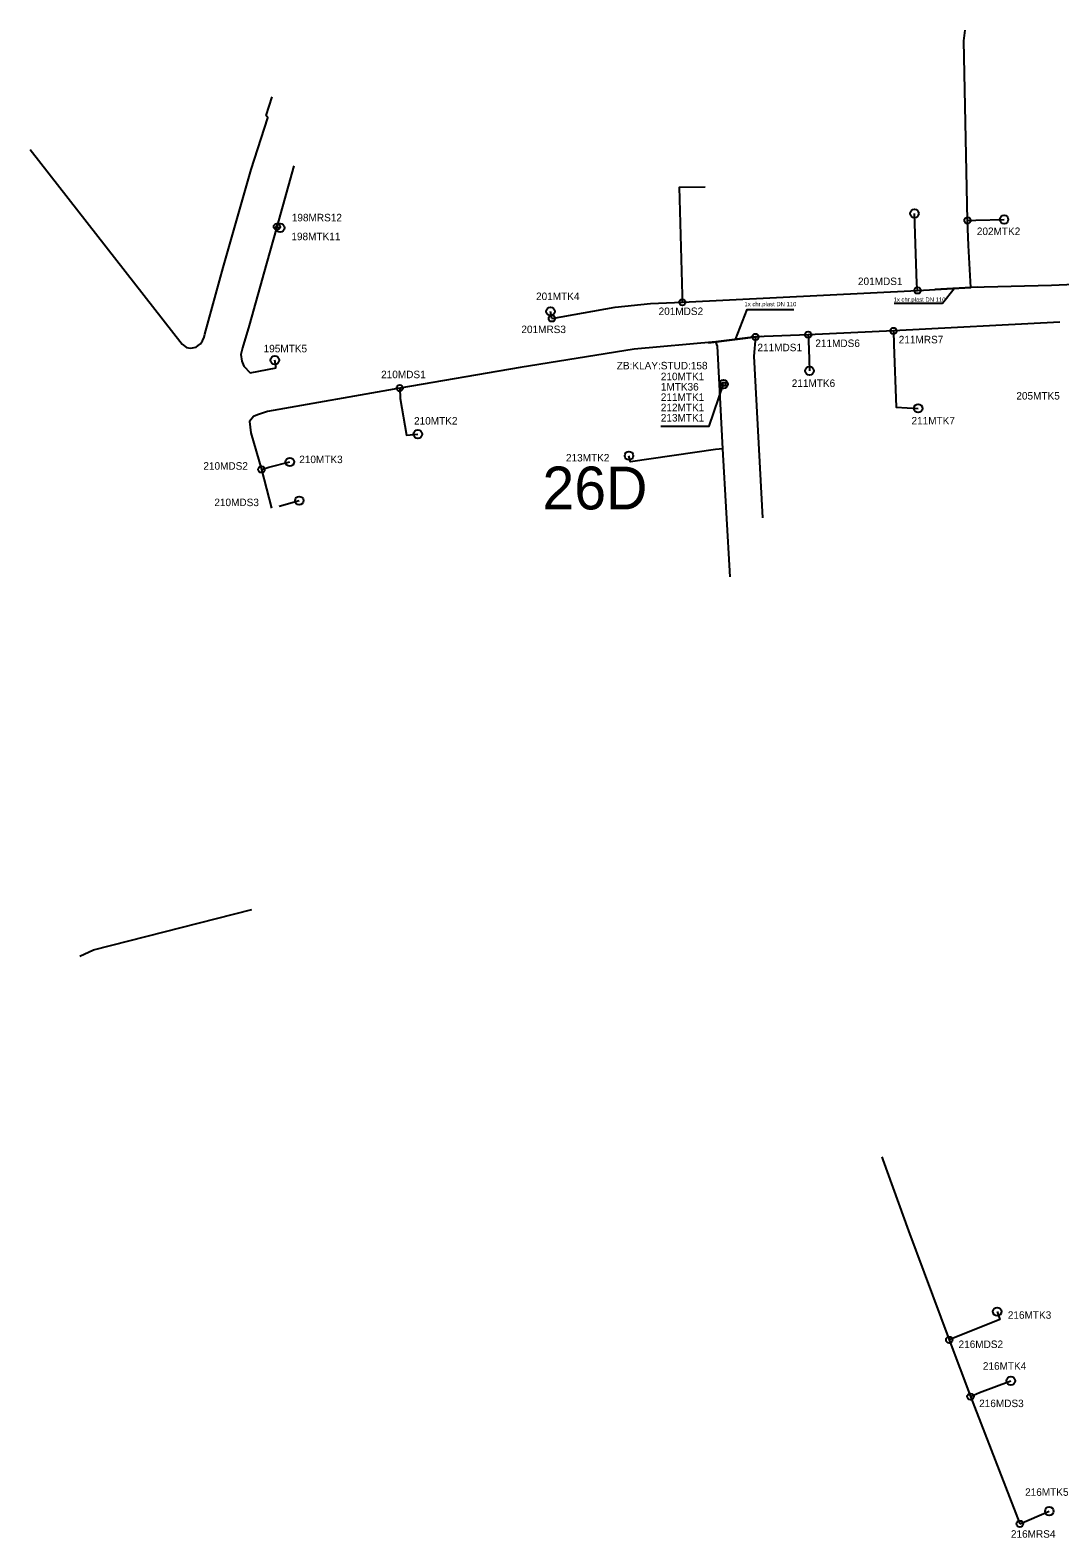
# Model space of a CAD drawing. Extents: x -835291 to -833547, y -1108367 to -1106510.
# Drawn here: x -834054.6 to -833814, y -1108018.1 to -1107665.9 of the extents above; entities that cross this region are included whole.
import ezdxf

# ---------------------------------------------------------------- set-up
doc = ezdxf.new("R2010")
doc.units = 0
for name, color, linetype in [('Vrstva 1', 7, 'Continuous'), ('Vrstva 12', 7, 'Continuous'), ('Vrstva 13', 7, 'Continuous'), ('Vrstva 18', 7, 'Continuous'), ('Vrstva 21', 7, 'Continuous'), ('Vrstva 3', 7, 'Continuous'), ('Vrstva 5', 7, 'Continuous')]:
    doc.layers.add(name, color=color, linetype=linetype)

msp = doc.modelspace()

# ---------------------------------------------------------------- linework, layer by layer
at = {"layer": 'Vrstva 1'}
for p, q in [((-833992.95, -1107697.61), (-833996.91, -1107711.85)), ((-833835.57, -1107710.38), (-833833.62, -1107710.35)), ((-833996.91, -1107711.85), (-833996.15, -1107712.11)), ((-833902.2, -1107729.52), (-833847.29, -1107726.75)), ((-833902.2, -1107729.52), (-833902.17, -1107727.88)), ((-833847.29, -1107726.75), (-833847.41, -1107725.17)), ((-833847.29, -1107726.75), (-833834.83, -1107726.06)), ((-833932.68, -1107733.29), (-833932.99, -1107731.64)), ((-833814.02, -1107734.16), (-833852.9, -1107736.21)), ((-833885.12, -1107737.61), (-833894.39, -1107738.75)), ((-833872.82, -1107737.08), (-833885.12, -1107737.61)), ((-833852.9, -1107736.21), (-833872.82, -1107737.08)), ((-833872.82, -1107737.08), (-833872.64, -1107740.35)), ((-833852.9, -1107736.21), (-833852.82, -1107739.35)), ((-834003.19, -1107745.97), (-833997.11, -1107744.83)), ((-833997.11, -1107744.83), (-833997.41, -1107743.01)), ((-833968.23, -1107749.58), (-833968.11, -1107751.98)), ((-833893.56, -1107748.69), (-833892.56, -1107748.65)), ((-833892.74, -1107763.77), (-833893.56, -1107748.69)), ((-833892.74, -1107763.77), (-833894.48, -1107763.9)), ((-833891.07, -1107793.68), (-833892.74, -1107763.77)), ((-834000.53, -1107768.56), (-833998.82, -1107768.04)), ((-834000.53, -1107768.56), (-833998.17, -1107777.62)), ((-833839.85, -1107971.91), (-833834.9, -1107985.16)), ((-833834.9, -1107985.16), (-833832.76, -1107984.23)), ((-833834.9, -1107985.16), (-833823.37, -1108014.89)), ((-833823.37, -1108014.89), (-833821.22, -1108013.92))]:
    msp.add_line(p, q, dxfattribs=at)
for points in [[(-833835.57, -1107710.38), (-833836.47, -1107668.46), (-833836.13, -1107665.94)], [(-834054.56, -1107693.86), (-834019.06, -1107739.26), (-834018.04, -1107740.06), (-834017.07, -1107740.22), (-834015.81, -1107740.02), (-834015.28, -1107739.62), (-834014.75, -1107739.22), (-834014.27, -1107738.52), (-834013.88, -1107737.65), (-834013.75, -1107736.97), (-834009.44, -1107721.37), (-834002.94, -1107698.53), (-833999, -1107686.41), (-833999.43, -1107685.91), (-833998.01, -1107681.53)], [(-833834.83, -1107726.06), (-833835.36, -1107716.25), (-833835.57, -1107710.38)], [(-833996.91, -1107711.85), (-833999.31, -1107720.42), (-834003.39, -1107734.93)], [(-833780.16, -1107724.03), (-833815.95, -1107725.61), (-833834.83, -1107726.06)], [(-833932.68, -1107733.29), (-833917.9, -1107730.65), (-833909.61, -1107729.79), (-833902.2, -1107729.52)], [(-834003.39, -1107734.93), (-834004.94, -1107740.19), (-834005.38, -1107741.69), (-834005.14, -1107743.29)], [(-833894.39, -1107738.75), (-833913.49, -1107740.44), (-833940.08, -1107744.71), (-833968.23, -1107749.58)], [(-833893.56, -1107748.69), (-833893.99, -1107739.8), (-833894.39, -1107738.75)], [(-833885.12, -1107737.61), (-833885.51, -1107742.13), (-833883.47, -1107779.86)], [(-834005.14, -1107743.29), (-834005.14, -1107743.29), (-834005.14, -1107743.29), (-834004.66, -1107744.45), (-834003.19, -1107745.97)], [(-833968.23, -1107749.58), (-833999.15, -1107754.99), (-834001.44, -1107755.82)], [(-834001.44, -1107755.82), (-834002.39, -1107756.17), (-834003.31, -1107757.37), (-834002.98, -1107760), (-834000.53, -1107768.56)], [(-834042.98, -1107882.24), (-834039.74, -1107880.76), (-834002.78, -1107871.35)], [(-833855.59, -1107929.16), (-833855.41, -1107929.83), (-833849.4, -1107946.41), (-833845.71, -1107956.24), (-833839.85, -1107971.91)]]:
    msp.add_lwpolyline(points, dxfattribs=at)
at = {"layer": 'Vrstva 12'}
for p, q in [((-833833.31, -1107725.97), (-833843.2, -1107726.52)), ((-833896.11, -1107738.97), (-833883.79, -1107737.45))]:
    msp.add_line(p, q, dxfattribs=at)
at = {"layer": 'Vrstva 13'}
for points in [[(-833852.72, -1107729.69), (-833841.47, -1107729.69), (-833838.72, -1107726.27)], [(-833889.75, -1107738.18), (-833887.05, -1107731.17), (-833876.13, -1107731.17)]]:
    msp.add_lwpolyline(points, dxfattribs=at)
at = {"layer": 'Vrstva 21'}
for p, q in [((-833847.41, -1107725.17), (-833848, -1107708.79)), ((-833833.62, -1107710.35), (-833827.06, -1107710.18)), ((-833872.64, -1107740.35), (-833872.5, -1107745.53)), ((-833998.82, -1107768.04), (-833993.89, -1107766.82)), ((-833996.42, -1107777.17), (-833991.68, -1107775.85)), ((-833832.76, -1107984.23), (-833825.45, -1107981.48)), ((-833821.22, -1108013.92), (-833816.48, -1108011.92))]:
    msp.add_line(p, q, dxfattribs=at)
for points in [[(-833902.17, -1107727.88), (-833902.85, -1107702.64), (-833896.85, -1107702.55)], [(-833852.82, -1107739.35), (-833852.24, -1107754.02), (-833847.11, -1107754.29)], [(-833968.11, -1107751.98), (-833966.61, -1107760.52), (-833964, -1107760.3)], [(-833894.48, -1107763.9), (-833914.33, -1107766.8), (-833914.67, -1107765.35)], [(-833828.64, -1107965.31), (-833828.04, -1107967.15), (-833839.85, -1107971.91)]]:
    msp.add_lwpolyline(points, dxfattribs=at)
at = {"layer": 'Vrstva 3'}
msp.add_lwpolyline([(-833892.97, -1107748.23), (-833892.15, -1107748.23), (-833892.15, -1107749.06), (-833892.97, -1107749.06)], close=True, dxfattribs=at)
for centre, radius in [((-833848, -1107708.79), 1), ((-833835.57, -1107710.38), 0.75), ((-833827.06, -1107710.18), 1), ((-833996.91, -1107711.85), 0.75), ((-833996.15, -1107712.11), 1), ((-833847.29, -1107726.75), 0.75), ((-833932.99, -1107731.64), 1), ((-833902.2, -1107729.52), 0.75), ((-833932.68, -1107733.29), 0.75), ((-833852.9, -1107736.21), 0.75), ((-833885.12, -1107737.61), 0.75), ((-833872.82, -1107737.08), 0.75), ((-833997.41, -1107743.01), 1), ((-833872.5, -1107745.53), 1), ((-833968.24, -1107749.55), 0.75), ((-833892.56, -1107748.65), 1), ((-833847.11, -1107754.29), 1), ((-833964, -1107760.3), 1), ((-833993.89, -1107766.82), 1), ((-833914.67, -1107765.35), 1), ((-834000.53, -1107768.56), 0.75), ((-833991.68, -1107775.85), 1), ((-833828.64, -1107965.31), 1), ((-833839.85, -1107971.91), 0.75), ((-833825.45, -1107981.48), 1), ((-833834.9, -1107985.16), 0.75), ((-833816.48, -1108011.92), 1), ((-833823.37, -1108014.89), 0.75)]:
    msp.add_circle(centre, radius, dxfattribs=at)
at = {"layer": 'Vrstva 5'}
msp.add_lwpolyline([(-833907.21, -1107758.49), (-833895.95, -1107758.49), (-833892.56, -1107748.65)], dxfattribs=at)

# ---------------------------------------------------------------- texts
at = {"layer": 'Vrstva 13'}
for p in [(-833852.86, -1107729.38), (-833887.69, -1107730.43)]:
    msp.add_text('1x chr.plast DN 110', height=1, dxfattribs=at).set_placement(p)
at = {"layer": 'Vrstva 18'}
msp.add_text('26D', height=10, dxfattribs=at).set_placement((-833934.89, -1107777.9))
at = {"layer": 'Vrstva 5'}
for s, p in [('198MRS12', (-833993.44, -1107710.6)), ('198MTK11', (-833993.53, -1107715.01)), ('202MTK2', (-833833.41, -1107713.8)), ('201MDS1', (-833861.18, -1107725.49)), ('201MTK4', (-833936.38, -1107728.99)), ('201MDS2', (-833907.75, -1107732.49)), ('201MRS3', (-833939.81, -1107736.71)), ('211MDS1', (-833884.66, -1107740.95)), ('211MDS6', (-833871.14, -1107739.96)), ('211MRS7', (-833851.65, -1107739.1)), ('195MTK5', (-834000.02, -1107741.2)), ('210MDS1', (-833972.57, -1107747.25)), ('ZB:KLAY:STUD:158', (-833917.52, -1107745.18)), ('210MTK1', (-833907.23, -1107747.72)), ('1MTK36', (-833907.23, -1107750.13)), ('211MTK6', (-833876.65, -1107749.29)), ('211MTK1', (-833907.23, -1107752.55)), ('212MTK1', (-833907.23, -1107754.96)), ('205MTK5', (-833824.18, -1107752.24)), ('210MTK2', (-833964.88, -1107758.08)), ('213MTK1', (-833907.23, -1107757.37)), ('211MTK7', (-833848.67, -1107758.05)), ('210MDS2', (-834014.1, -1107768.62)), ('210MTK3', (-833991.7, -1107767.09)), ('213MTK2', (-833929.39, -1107766.7)), ('210MDS3', (-834011.53, -1107777.13)), ('216MTK3', (-833826.17, -1107966.97)), ('216MDS2', (-833837.68, -1107973.8)), ('216MTK4', (-833832, -1107978.87)), ('216MDS3', (-833832.87, -1107987.61)), ('216MTK5', (-833822.13, -1108008.33)), ('216MRS4', (-833825.45, -1108018.12))]:
    msp.add_text(s, height=1.75, dxfattribs=at).set_placement(p)

doc.saveas('drawing.dxf')
